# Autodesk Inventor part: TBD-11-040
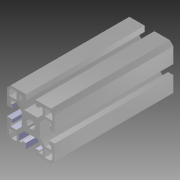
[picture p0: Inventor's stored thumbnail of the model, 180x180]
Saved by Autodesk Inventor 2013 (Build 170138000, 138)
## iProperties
Created: 2004-10
Material: Aluminium - 6061
Document SubType Name: Modeling
Designer: Autodesk, Inc.
Manufacturer: Standard
Standards Organization: Custom
Description: 40 SERIES, 40X40, HEAVY PROFILE
Stock Number: 11-040
Catalog Web Link: http://www.parker.com/ead/cm1.asp?cmid=809
Vendor: PARKER IPS
Part Number: TBD-11-040
Mass: 179.948 g
Surface Area: 483.565 cm^2
Volume: 66.4013 cm^3
Density: 2.71 g/cm^3
CAGE: 1LJX3
Dept. ID: Product Design
Description #2: ---
Finish #1: ---
Finish #2: ---
Material ID: ---
Project Number: ---
Length: 508.000 mm
Author: Autodesk, Inc.
Revision Number: --
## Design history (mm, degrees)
derived "40 Series Profiles.ipt"
body "Solid1"
tag "TaggingFeature2"
feature "Solid1::40 Series Profiles.ipt" dims "ScaleForDerivedMember" = 10
other parameters: "Length" = 508
